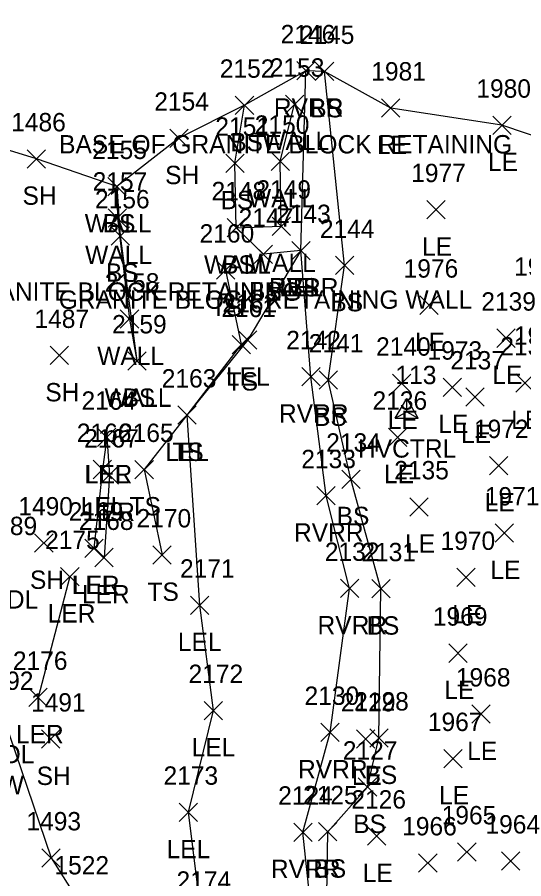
# Model space of a CAD drawing. Extents: x 1638344 to 1639591, y 610835 to 612202.
# Drawn here: x 1638637.1 to 1638692.3, y 611741.3 to 611835.2 of the extents above; entities that cross this region are included whole.
import ezdxf

# ---------------------------------------------------------------- set-up
doc = ezdxf.new("R2010")
doc.units = 0
for name, color, linetype in [('C_A', 7, 'Continuous'), ('C_I', 7, 'Continuous'), ('CPSM', 7, 'Continuous'), ('L_A', 7, 'Continuous'), ('L_C', 7, 'Continuous'), ('L_I', 7, 'Continuous'), ('L_TIC', 7, 'Continuous'), ('LARO', 7, 'Continuous'), ('LAWA', 7, 'Continuous'), ('LAWE', 7, 'Continuous'), ('LELB', 7, 'Continuous'), ('LSOGP', 7, 'Continuous'), ('LW', 7, 'Continuous')]:
    doc.layers.add(name, color=color, linetype=linetype)

msp = doc.modelspace()

# ---------------------------------------------------------------- linework, layer by layer
at = {"layer": 'CPSM'}
for p, q in [((1638678.296, 611791.472), (1638679.546, 611793.637)), ((1638680.796, 611791.472), (1638679.546, 611793.637)), ((1638679.546, 611792.193), (1638679.546, 611793.637)), ((1638678.296, 611791.472), (1638679.546, 611792.193)), ((1638679.546, 611792.193), (1638679.546, 611792.193)), ((1638679.546, 611792.193), (1638680.796, 611791.472)), ((1638678.296, 611791.472), (1638680.796, 611791.472))]:
    msp.add_line(p, q, dxfattribs=at)
at = {"layer": 'L_TIC'}
for points in [[(1638667.561, 611828.322), (1638669.561, 611830.322)], [(1638669.561, 611828.322), (1638667.561, 611830.322)], [(1638669.59, 611828.25), (1638671.59, 611830.25)], [(1638671.59, 611828.25), (1638669.59, 611830.25)], [(1638660.879, 611824.565), (1638662.879, 611826.565)], [(1638662.879, 611824.565), (1638660.879, 611826.565)], [(1638666.326, 611824.682), (1638668.326, 611826.682)], [(1638668.326, 611824.682), (1638666.326, 611826.682)], [(1638676.812, 611824.266), (1638678.812, 611826.266)], [(1638678.812, 611824.266), (1638676.812, 611826.266)], [(1638688.906, 611822.394), (1638690.906, 611824.394)], [(1638690.906, 611822.394), (1638688.906, 611824.394)], [(1638653.744, 611820.976), (1638655.744, 611822.976)], [(1638655.744, 611820.976), (1638653.744, 611822.976)], [(1638638.216, 611818.73), (1638640.216, 611820.73)], [(1638640.216, 611818.73), (1638638.216, 611820.73)], [(1638659.827, 611818.248), (1638661.827, 611820.248)], [(1638661.827, 611818.248), (1638659.827, 611820.248)], [(1638664.776, 611818.465), (1638666.776, 611820.465)], [(1638666.776, 611818.465), (1638664.776, 611820.465)], [(1638646.991, 611815.714), (1638648.991, 611817.714)], [(1638648.991, 611815.714), (1638646.991, 611817.714)], [(1638646.991, 611815.714), (1638648.991, 611817.714)], [(1638648.991, 611815.714), (1638646.991, 611817.714)], [(1638681.722, 611813.197), (1638683.722, 611815.197)], [(1638683.722, 611813.197), (1638681.722, 611815.197)], [(1638647.033, 611812.277), (1638649.033, 611814.277)], [(1638649.033, 611812.277), (1638647.033, 611814.277)], [(1638664.874, 611811.397), (1638666.874, 611813.397)], [(1638666.874, 611811.397), (1638664.874, 611813.397)], [(1638647.344, 611810.341), (1638649.344, 611812.341)], [(1638649.344, 611810.341), (1638647.344, 611812.341)], [(1638659.98, 611811.226), (1638661.98, 611813.226)], [(1638661.98, 611811.226), (1638659.98, 611813.226)], [(1638659.98, 611811.226), (1638661.98, 611813.226)], [(1638661.98, 611811.226), (1638659.98, 611813.226)], [(1638667.019, 611808.745), (1638669.019, 611810.745)], [(1638669.019, 611808.745), (1638667.019, 611810.745)], [(1638667.019, 611808.745), (1638669.019, 611810.745)], [(1638669.019, 611808.745), (1638667.019, 611810.745)], [(1638667.019, 611808.745), (1638669.019, 611810.745)], [(1638669.019, 611808.745), (1638667.019, 611810.745)], [(1638662.933, 611808.335), (1638664.933, 611810.335)], [(1638664.933, 611808.335), (1638662.933, 611810.335)], [(1638658.811, 611806.612), (1638660.811, 611808.612)], [(1638660.811, 611806.612), (1638658.811, 611808.612)], [(1638671.782, 611807.122), (1638673.782, 611809.122)], [(1638673.782, 611807.122), (1638671.782, 611809.122)], [(1638680.955, 611802.795), (1638682.955, 611804.795)], [(1638682.955, 611802.795), (1638680.955, 611804.795)], [(1638648.352, 611801.277), (1638650.352, 611803.277)], [(1638650.352, 611801.277), (1638648.352, 611803.277)], [(1638689.368, 611799.201), (1638691.368, 611801.201)], [(1638691.368, 611799.201), (1638689.368, 611801.201)], [(1638660.526, 611798.495), (1638662.526, 611800.495)], [(1638662.526, 611798.495), (1638660.526, 611800.495)], [(1638661.223, 611799.014), (1638663.223, 611801.014)], [(1638663.223, 611799.014), (1638661.223, 611801.014)], [(1638640.696, 611797.316), (1638642.696, 611799.316)], [(1638642.696, 611797.316), (1638640.696, 611799.316)], [(1638649.154, 611796.722), (1638651.154, 611798.722)], [(1638651.154, 611796.722), (1638649.154, 611798.722)], [(1638649.154, 611796.722), (1638651.154, 611798.722)], [(1638651.154, 611796.722), (1638649.154, 611798.722)], [(1638668.117, 611795.001), (1638670.117, 611797.001)], [(1638670.117, 611795.001), (1638668.117, 611797.001)], [(1638670, 611794.643), (1638672, 611796.643)], [(1638672, 611794.643), (1638670, 611796.643)], [(1638677.987, 611794.293), (1638679.987, 611796.293)], [(1638679.987, 611794.293), (1638677.987, 611796.293)], [(1638683.498, 611793.862), (1638685.498, 611795.862)], [(1638685.498, 611793.862), (1638683.498, 611795.862)], [(1638691.432, 611794.319), (1638693.432, 611796.319)], [(1638693.432, 611794.319), (1638691.432, 611796.319)], [(1638685.984, 611792.795), (1638687.984, 611794.795)], [(1638687.984, 611792.795), (1638685.984, 611794.795)], [(1638654.604, 611790.826), (1638656.604, 611792.826)], [(1638656.604, 611790.826), (1638654.604, 611792.826)], [(1638654.604, 611790.826), (1638656.604, 611792.826)], [(1638656.604, 611790.826), (1638654.604, 611792.826)], [(1638645.867, 611788.404), (1638647.867, 611790.404)], [(1638647.867, 611788.404), (1638645.867, 611790.404)], [(1638645.867, 611788.404), (1638647.867, 611790.404)], [(1638647.867, 611788.404), (1638645.867, 611790.404)], [(1638677.568, 611788.406), (1638679.568, 611790.406)], [(1638679.568, 611788.406), (1638677.568, 611790.406)], [(1638688.555, 611785.323), (1638690.555, 611787.323)], [(1638690.555, 611785.323), (1638688.555, 611787.323)], [(1638645.406, 611784.897), (1638647.406, 611786.897)], [(1638647.406, 611784.897), (1638645.406, 611786.897)], [(1638646.161, 611784.29), (1638648.161, 611786.29)], [(1638648.161, 611784.29), (1638646.161, 611786.29)], [(1638649.949, 611784.894), (1638651.949, 611786.894)], [(1638651.949, 611784.894), (1638649.949, 611786.894)], [(1638672.469, 611783.839), (1638674.469, 611785.839)], [(1638674.469, 611783.839), (1638672.469, 611785.839)], [(1638669.756, 611782.04), (1638671.756, 611784.04)], [(1638671.756, 611782.04), (1638669.756, 611784.04)], [(1638679.879, 611780.825), (1638681.879, 611782.825)], [(1638681.879, 611780.825), (1638679.879, 611782.825)], [(1638689.175, 611777.982), (1638691.175, 611779.982)], [(1638691.175, 611777.982), (1638689.175, 611779.982)], [(1638639.024, 611776.892), (1638641.024, 611778.892)], [(1638641.024, 611776.892), (1638639.024, 611778.892)], [(1638644.483, 611776.324), (1638646.483, 611778.324)], [(1638646.483, 611776.324), (1638644.483, 611778.324)], [(1638644.483, 611776.324), (1638646.483, 611778.324)], [(1638646.483, 611776.324), (1638644.483, 611778.324)], [(1638645.583, 611775.312), (1638647.583, 611777.312)], [(1638647.583, 611775.312), (1638645.583, 611777.312)], [(1638651.901, 611775.588), (1638653.901, 611777.588)], [(1638653.901, 611775.588), (1638651.901, 611777.588)], [(1638641.854, 611773.231), (1638643.854, 611775.231)], [(1638643.854, 611773.231), (1638641.854, 611775.231)], [(1638685.007, 611773.139), (1638687.007, 611775.139)], [(1638687.007, 611773.139), (1638685.007, 611775.139)], [(1638672.317, 611771.941), (1638674.317, 611773.941)], [(1638674.317, 611771.941), (1638672.317, 611773.941)], [(1638675.731, 611771.908), (1638677.731, 611773.908)], [(1638677.731, 611771.908), (1638675.731, 611773.908)], [(1638655.981, 611770.118), (1638657.981, 611772.118)], [(1638657.981, 611770.118), (1638655.981, 611772.118)], [(1638684.139, 611764.892), (1638686.139, 611766.892)], [(1638686.139, 611764.892), (1638684.139, 611766.892)], [(1638638.401, 611760.074), (1638640.401, 611762.074)], [(1638640.401, 611760.074), (1638638.401, 611762.074)], [(1638657.475, 611758.642), (1638659.475, 611760.642)], [(1638659.475, 611758.642), (1638657.475, 611760.642)], [(1638686.639, 611758.262), (1638688.639, 611760.262)], [(1638688.639, 611758.262), (1638686.639, 611760.262)], [(1638670.195, 611756.256), (1638672.195, 611758.256)], [(1638672.195, 611756.256), (1638670.195, 611758.256)], [(1638639.753, 611755.535), (1638641.753, 611757.535)], [(1638641.753, 611755.535), (1638639.753, 611757.535)], [(1638674.078, 611755.551), (1638676.078, 611757.551)], [(1638676.078, 611755.551), (1638674.078, 611757.551)], [(1638675.509, 611755.644), (1638677.509, 611757.644)], [(1638677.509, 611755.644), (1638675.509, 611757.644)], [(1638683.585, 611753.413), (1638685.585, 611755.413)], [(1638685.585, 611753.413), (1638683.585, 611755.413)], [(1638674.273, 611750.303), (1638676.273, 611752.303)], [(1638676.273, 611750.303), (1638674.273, 611752.303)], [(1638654.748, 611747.56), (1638656.748, 611749.56)], [(1638656.748, 611747.56), (1638654.748, 611749.56)], [(1638667.237, 611745.392), (1638669.237, 611747.392)], [(1638669.237, 611745.392), (1638667.237, 611747.392)], [(1638669.942, 611745.441), (1638671.942, 611747.441)], [(1638671.942, 611745.441), (1638669.942, 611747.441)], [(1638675.263, 611744.967), (1638677.263, 611746.967)], [(1638677.263, 611744.967), (1638675.263, 611746.967)], [(1638685.091, 611743.247), (1638687.091, 611745.247)], [(1638687.091, 611743.247), (1638685.091, 611745.247)], [(1638639.82, 611742.59), (1638641.82, 611744.59)], [(1638641.82, 611742.59), (1638639.82, 611744.59)], [(1638680.844, 611742.045), (1638682.844, 611744.045)], [(1638682.844, 611742.045), (1638680.844, 611744.045)], [(1638689.857, 611742.249), (1638691.857, 611744.249)], [(1638691.857, 611742.249), (1638689.857, 611744.249)]]:
    msp.add_lwpolyline(points, dxfattribs=at)
at = {"layer": 'LARO'}
for points in [[(1638668.019, 611809.745), (1638662.223, 611800.014), (1638655.604, 611791.826), (1638656.981, 611771.118), (1638658.475, 611759.642), (1638655.748, 611748.56), (1638657.167, 611737.126)], [(1638646.867, 611789.404), (1638646.406, 611785.897), (1638645.483, 611777.324)], [(1638646.867, 611789.404), (1638647.161, 611785.29), (1638646.583, 611776.312), (1638645.483, 611777.324)], [(1638642.854, 611774.231), (1638639.401, 611761.074)]]:
    msp.add_lwpolyline(points, dxfattribs=at)
at = {"layer": 'LAWA'}
msp.add_lwpolyline([(1638628.579, 611823.011), (1638631.205, 611793.982), (1638636.051, 611775.752), (1638635.636, 611758.892), (1638640.82, 611743.59), (1638643.87, 611738.789), (1638644.553, 611728.051), (1638647.989, 611718.924), (1638655.164, 611720.387)], dxfattribs=at)
at = {"layer": 'LAWE'}
msp.add_lwpolyline([(1638639.67, 611638.455), (1638651.909, 611645.684), (1638665.496, 611649.056), (1638676.655, 611655.904), (1638679.763, 611666.345), (1638680.738, 611673.208), (1638671.065, 611682.751), (1638669.589, 611691.757), (1638672.343, 611706.91), (1638673.822, 611718.895), (1638672.065, 611725.227), (1638669.72, 611732.484), (1638668.237, 611746.392), (1638671.195, 611757.256), (1638673.317, 611772.941), (1638670.756, 611783.04), (1638669.117, 611796.001), (1638668.019, 611809.745), (1638668.561, 611829.322)], dxfattribs=at)
at = {"layer": 'LELB'}
for points in [[(1638679.486, 611663.994), (1638681.736, 611674.726), (1638674.098, 611683.416), (1638671.48, 611693.048), (1638672.758, 611705.85), (1638674.815, 611720.343), (1638674.129, 611725.937), (1638670.752, 611732.595), (1638670.942, 611746.441), (1638675.273, 611751.303), (1638676.509, 611756.644), (1638676.731, 611772.908), (1638673.469, 611784.839), (1638671, 611795.643), (1638672.782, 611808.122), (1638670.59, 611829.25)], [(1638668.019, 611809.745), (1638663.933, 611809.335), (1638660.98, 611812.226), (1638660.827, 611819.248), (1638661.879, 611825.565)], [(1638647.991, 611816.714), (1638648.344, 611811.341), (1638650.154, 611797.722)], [(1638659.811, 611807.612), (1638661.526, 611799.495), (1638655.604, 611791.826), (1638650.949, 611785.894), (1638652.901, 611776.588)]]:
    msp.add_lwpolyline(points, dxfattribs=at)
at = {"layer": 'LSOGP'}
msp.add_lwpolyline([(1638742.435, 611835.158), (1638718.339, 611821.861), (1638715.698, 611824.36), (1638711.099, 611825.207), (1638697.729, 611820.746), (1638689.906, 611823.394), (1638677.812, 611825.266), (1638670.59, 611829.25), (1638668.561, 611829.322), (1638661.879, 611825.565), (1638654.744, 611821.976), (1638647.991, 611816.714), (1638639.216, 611819.73), (1638628.579, 611823.011), (1638624.708, 611822.742), (1638622.542, 611822.46), (1638614.597, 611821.058), (1638611.675, 611820.94), (1638608.438, 611821.099), (1638593.01, 611817.319), (1638581.952, 611815.473), (1638593.253, 611782.913), (1638592.058, 611751.785), (1638571.096, 611733.73)], dxfattribs=at)
at = {"layer": 'LW'}
for points in [[(1638660.98, 611812.226), (1638665.874, 611812.397), (1638665.776, 611819.465), (1638667.326, 611825.682)], [(1638647.991, 611816.714), (1638648.033, 611813.277), (1638649.352, 611802.277), (1638650.154, 611797.722)]]:
    msp.add_lwpolyline(points, dxfattribs=at)

# ---------------------------------------------------------------- texts
at = {"layer": 'C_A'}
msp.add_text('HVCTRL', height=2, dxfattribs=at).set_placement((1638674.239, 611787.193))
at = {"layer": 'C_I'}
msp.add_text('113', height=2, dxfattribs=at).set_placement((1638678.318, 611795.193))
at = {"layer": 'L_A'}
for s, p in [('RVRR', (1638665.073, 611824.322)), ('BS', (1638669.031, 611824.25)), ('WALL', (1638663.814, 611820.682)), ('BS', (1638660.32, 611820.565)), ('LE', (1638676.3, 611820.266)), ('LE', (1638688.394, 611818.394)), ('SH', (1638653.232, 611816.976)), ('SH', (1638637.704, 611814.73)), ('BS', (1638659.268, 611814.248)), ('WALL', (1638662.264, 611814.465)), ('WALL', (1638644.479, 611811.714)), ('BS', (1638646.432, 611811.714)), ('LE', (1638681.21, 611809.197)), ('WALL', (1638644.522, 611808.277)), ('WALL', (1638657.469, 611807.226)), ('BS', (1638659.421, 611807.226)), ('WALL', (1638662.362, 611807.397)), ('BS', (1638646.785, 611806.341)), ('RVRR', (1638664.531, 611804.745)), ('LEL', (1638665.657, 611804.745)), ('BS', (1638666.46, 611804.745)), ('BS', (1638662.374, 611804.335)), ('BS', (1638671.223, 611803.122)), ('TS', (1638658.221, 611802.612)), ('LE', (1638680.443, 611798.795)), ('WALL', (1638645.84, 611797.277)), ('TS', (1638659.936, 611794.495)), ('LEL', (1638659.861, 611795.014)), ('LE', (1638688.857, 611795.201)), ('SH', (1638640.185, 611793.316)), ('WALL', (1638646.643, 611792.722)), ('BS', (1638648.595, 611792.722)), ('RVRR', (1638665.629, 611791.001)), ('BS', (1638669.441, 611790.643)), ('LE', (1638677.475, 611790.293)), ('LE', (1638682.986, 611789.862)), ('LE', (1638690.92, 611790.319)), ('LE', (1638685.472, 611788.795)), ('LEL', (1638653.242, 611786.826)), ('TS', (1638654.014, 611786.826)), ('LER', (1638644.45, 611784.404)), ('LEL', (1638644.505, 611784.404)), ('LE', (1638677.056, 611784.406)), ('LE', (1638688.043, 611781.323)), ('LEL', (1638644.043, 611780.897)), ('TS', (1638649.359, 611780.894)), ('LER', (1638644.743, 611780.29)), ('BS', (1638671.91, 611779.839)), ('RVRR', (1638667.268, 611778.04)), ('LE', (1638679.368, 611776.825)), ('LE', (1638688.663, 611773.982)), ('SH', (1638638.512, 611772.892)), ('LER', (1638643.065, 611772.324)), ('LEL', (1638643.12, 611772.324)), ('LER', (1638644.166, 611771.312)), ('TS', (1638651.31, 611771.588)), ('WDL', (1638633.468, 611770.752)), ('LER', (1638640.436, 611769.231)), ('LE', (1638684.495, 611769.139)), ('RVRR', (1638669.829, 611767.941)), ('BS', (1638675.172, 611767.908)), ('LEL', (1638654.619, 611766.118)), ('LE', (1638683.627, 611760.892)), ('LER', (1638636.984, 611756.074)), ('LEL', (1638656.113, 611754.642)), ('LE', (1638686.128, 611754.262)), ('WDL', (1638633.053, 611753.892)), ('RVRR', (1638667.707, 611752.256)), ('SH', (1638639.242, 611751.535)), ('LE', (1638673.566, 611751.551)), ('BS', (1638674.95, 611751.644)), ('FNWW', (1638629.241, 611750.534)), ('LE', (1638683.073, 611749.413)), ('BS', (1638673.714, 611746.303)), ('LEL', (1638653.386, 611743.56)), ('RVRR', (1638664.749, 611741.392)), ('BS', (1638669.383, 611741.441)), ('LE', (1638674.751, 611740.967))]:
    msp.add_text(s, height=2, dxfattribs=at).set_placement(p)
at = {"layer": 'L_C'}
for s, p in [('BASE OF GRANITE BLOCK RETAINING', (1638641.687, 611820.322)), ('OLD GRANITE BLOCK RETAINING', (1638624.829, 611804.277)), ('GRANITE BLOCK RETAINING WALL', (1638641.653, 611803.397))]:
    msp.add_text(s, height=2, dxfattribs=at).set_placement(p)
at = {"layer": 'L_I'}
for s, p in [('2146', (1638665.813, 611832.322)), ('2145', (1638667.897, 611832.25)), ('2152', (1638659.186, 611828.565)), ('2153', (1638664.633, 611828.682)), ('1981', (1638675.686, 611828.266)), ('1980', (1638687.126, 611826.394)), ('2154', (1638652.051, 611824.976)), ('1486', (1638636.468, 611822.73)), ('2151', (1638658.701, 611822.248)), ('2150', (1638662.997, 611822.465)), ('2155', (1638645.298, 611819.714)), ('2155', (1638645.298, 611819.714)), ('1977', (1638680.029, 611817.197)), ('2157', (1638645.34, 611816.277)), ('2148', (1638658.288, 611815.226)), ('2148', (1638658.288, 611815.226)), ('2149', (1638663.173, 611815.397)), ('2156', (1638645.596, 611814.341)), ('2147', (1638661.24, 611812.335)), ('2143', (1638665.326, 611812.745)), ('2143', (1638665.326, 611812.745)), ('2143', (1638665.326, 611812.745)), ('2160', (1638656.985, 611810.612)), ('2144', (1638670.089, 611811.122)), ('1976', (1638679.207, 611806.795)), ('1975', (1638691.235, 611807.004)), ('2158', (1638646.659, 611805.277)), ('2162', (1638659.483, 611803.014)), ('2139', (1638687.668, 611803.201)), ('2161', (1638659.353, 611802.495)), ('1487', (1638639.003, 611801.316)), ('2159', (1638647.454, 611800.722)), ('2159', (1638647.454, 611800.722)), ('1974', (1638691.221, 611799.485)), ('2142', (1638666.424, 611799.001)), ('2141', (1638668.874, 611798.643)), ('2140', (1638676.207, 611798.293)), ('2138', (1638689.739, 611798.319)), ('1973', (1638681.805, 611797.862)), ('2137', (1638684.291, 611796.795)), ('2163', (1638652.864, 611794.826)), ('2163', (1638652.864, 611794.826)), ('2164', (1638644.127, 611792.404)), ('2164', (1638644.127, 611792.404)), ('2136', (1638675.82, 611792.406)), ('2166', (1638643.61, 611788.897)), ('2165', (1638648.209, 611788.894)), ('1972', (1638686.862, 611789.323)), ('2167', (1638644.421, 611788.29)), ('2134', (1638670.777, 611787.839)), ('2133', (1638668.063, 611786.04)), ('2135', (1638678.186, 611784.825)), ('1971', (1638688.049, 611781.982)), ('1490', (1638637.244, 611780.892)), ('2169', (1638642.735, 611780.324)), ('2169', (1638642.735, 611780.324)), ('2170', (1638650.121, 611779.588)), ('1489', (1638633.35, 611778.752)), ('2168', (1638643.843, 611779.312)), ('2175', (1638640.161, 611777.231)), ('1970', (1638683.227, 611777.139)), ('2132', (1638670.624, 611775.941)), ('2131', (1638674.605, 611775.908)), ('2171', (1638654.855, 611774.118)), ('1969', (1638682.39, 611768.892)), ('2176', (1638636.653, 611764.074)), ('2172', (1638655.783, 611762.642)), ('1492', (1638632.943, 611761.892)), ('1968', (1638684.899, 611762.262)), ('2130', (1638668.415, 611760.256)), ('2128', (1638673.816, 611759.644)), ('1491', (1638638.627, 611759.535)), ('2129', (1638672.377, 611759.551)), ('1967', (1638681.845, 611757.413)), ('2127', (1638672.58, 611754.303)), ('2173', (1638653.056, 611751.56)), ('2124', (1638665.544, 611749.392)), ('2125', (1638668.25, 611749.441)), ('2126', (1638673.515, 611748.967)), ('1493', (1638638.127, 611746.59)), ('1965', (1638683.351, 611747.247)), ('1966', (1638679.049, 611746.045)), ('1964', (1638688.117, 611746.249)), ('1522', (1638641.177, 611741.789)), ('1522', (1638641.177, 611741.789)), ('2174', (1638654.474, 611740.126)), ('2174', (1638654.474, 611740.126))]:
    msp.add_text(s, height=2, dxfattribs=at).set_placement(p)

doc.saveas('drawing.dxf')
